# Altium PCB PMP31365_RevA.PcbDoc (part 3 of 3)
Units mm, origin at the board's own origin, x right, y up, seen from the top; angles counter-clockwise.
Board outline 134.61 x 49.53 mm, 4 copper layers (Top Layer, Layer 1, Layer 2, Bottom Layer), stack 1.787 mm thick; 183 components, 83 nets, 384 pads, 167 vias.
Unrouted connection lines stored in the file: 14.
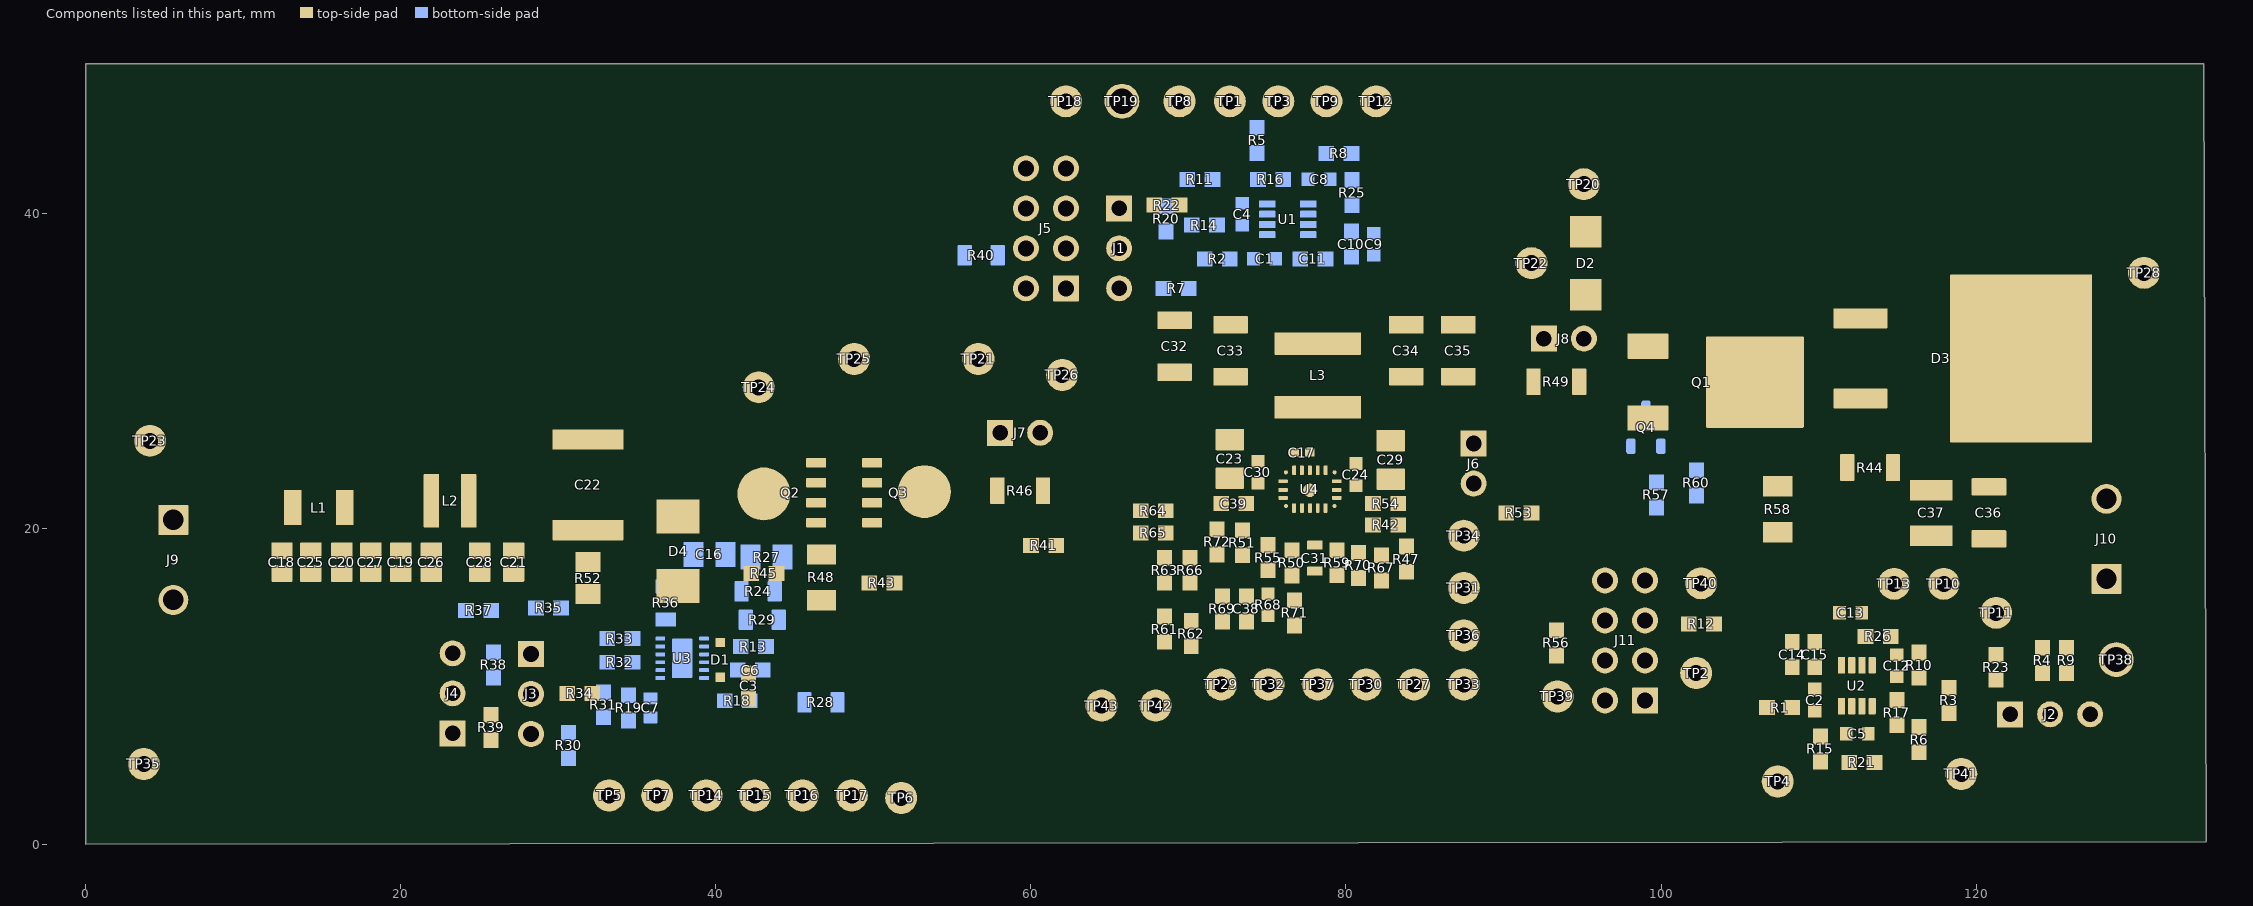
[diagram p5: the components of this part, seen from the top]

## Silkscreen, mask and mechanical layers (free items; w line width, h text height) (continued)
M10 Fab Notes:
  drawing of 189 lines, arcs and shapes, not listed
  text "DESIGN INFORMATION" at 741.376,161.675 h1.52
  text "MIN. TRACK WIDTH:" at 725.004,158.319 h1.52
  text "8" at 752.848,158.32 h1.52
  text "MIL" at 756.779,158.319 h1.52
  text "MIN. CLEARANCE:" at 725.004,155.167 h1.52
  text "7.874" at 748.5,155.167 h1.52
  text "MIL" at 756.779,155.167 h1.52
  text "MIN. VIA PAD SIZE:" at 725.004,152.014 h1.52
  text "24" at 752.087,152.014 h1.52
  text "MIL" at 756.779,152.014 h1.52
  text "0.05mm (2MIL)" at 742.657,148.714 h1.52
  text "MINIMUM ANNULAR RING" at 716.641,148.506 h1.52
  text "EXTERNAL" at 760.64,148.506 h1.52
  text "PER" at 721.721,145.708 h1.52
  text "IPC-D-275 CLASS 2 LEVEL C" at 727.309,145.708 h1.52
  text "MIL, HOLES" at 765.11,143.156 h1.52
  text "+/-" at 755.142,142.938 h1.52
  text "+/-" at 776.834,142.938 h1.52
  text "REGISTRATION TOLERANCES:" at 716.641,142.911 h1.52
  text "METAL" at 747.116,142.911 h1.52
  text "5" at 761.751,142.911 h1.52
  text "3" at 782.909,142.911 h1.52
  text "MIL" at 785.862,142.911 h1.52
  text "HOLE SIZE TOLERANCE (UNLESS OTHERWISE SPECIFIED):" at 716.641,140.414 h1.52
  text "+/-" at 776.834,140.341 h1.52
  text "3" at 782.909,140.314 h1.52
  text "MIL" at 785.862,140.314 h1.52
  text "MATERIAL:" at 714.742,136.818 h1.52
  text "FR-4 High Tg" at 739.798,133.553 h1.52
  text "X" at 736.129,133.35 h1.52
  text "FR-4" at 725.436,133.235 h1.52
  text "OTHER" at 763.231,133.235 h1.52
  text "62 MIL (1.6mm) +/-10%" at 733.566,129.602 h1.52
  text "X" at 730.516,129.54 h1.52
  text "THICKNESS:" at 716.641,129.394 h1.52
  text "OTHER" at 766.203,129.394 h1.52
  text "TOLERANCE:" at 716.641,125.88 h1.52
  text "X" at 738.187,125.88 h1.52
  text "ANSI IPC-6012 TYPE 3 CLASS 2" at 742.708,125.88 h1.52
  text "OTHER +/-" at 742.708,122.218 h1.52
  text "BOW & TWIST:" at 716.641,118.53 h1.52
  text "X" at 738.187,118.53 h1.52
  text "ANSI IPC-6012 TYPE 3 CLASS 2" at 742.708,118.53 h1.52
  text "OTHER +/-" at 742.708,114.804 h1.52
  text "DRILLING:" at 714.742,111.486 h1.52
  text "NC_DRILL FILES" at 759.472,108.815 h1.52
  text "REFERENCE:" at 716.641,108.715 h1.52
  text "X" at 733.335,108.712 h1.52
  text "AS SHOWN" at 737.856,108.715 h1.52
  text "X" at 756.221,108.715 h1.52
  text "OTHER" at 767.041,105.101 h1.52
  text "PTH COPPER THICKNESS:" at 716.633,105.012 h1.52
  text "X" at 745.57,105.012 h1.52
  text "20-30 um" at 748.821,105.012 h1.52
  text "BOARD FINISH:" at 714.742,101.263 h1.52
  text "SILKSCREEN:" at 718.685,98.466 h1.52
  text "X" at 743.013,98.466 h1.52
  text "TOP" at 745.984,98.466 h1.52
  text "X" at 755.967,98.466 h1.52
  text "BOTTOM" at 758.964,98.466 h1.52
  text "SILKSCREEN COLOR:" at 718.685,94.524 h1.52
  text "X" at 742.987,94.524 h1.52
  text "WHITE" at 745.984,94.524 h1.52
  text "OTHER" at 758.964,94.524 h1.52
  text "X" at 746.315,90.88 h1.52
  text "GREEN" at 749.312,90.88 h1.52
  text "OTHER" at 765.009,90.88 h1.52
  text "SOLDER RESIST COLOR:" at 718.685,90.706 h1.52
  text "X" at 746.315,86.962 h1.52
  text "MATTE" at 749.312,86.962 h1.52
  text "SEMI-GLOSS" at 764.997,86.946 h1.52
  text "IMMERSION GOLD (ENIG)" at 741.692,82.574 h1.52
  text "ENEPIG" at 775.665,82.39 h1.52
  text "SURFACE FINISH:" at 714.742,82.365 h1.52
  text "X" at 737.171,82.365 h1.52
  text "IMM. TIN/SILVER OR EQUIV" at 723.113,78.877 h1.52
  text "OTHER" at 759.472,78.777 h1.52
  text "ARRAY/PANEL:" at 714.742,74.831 h1.52
  text "CUT AND TRIM PER M1 BOARD OUTLINE" at 741.692,74.622 h1.52
  text "N.C. ROUTE" at 741.692,71.168 h1.52
  text "X" at 759.167,71.168 h1.52
  text "V. SCORE" at 763.688,71.168 h1.52
  text "CERTIFICATION:" at 714.742,67.888 h1.52
  text "MATERIALS AND WORKMANSHIP FOR ALL PCBS" at 733.157,67.888 h1.52
  text "TO MEET OR EXCEED THE REQUIREMENTS OF:" at 733.157,65.499 h1.52
  text "X" at 723.95,62.232 h1.52
  text "ANSI IPC-A-600F CLASS ->" at 727.201,62.232 h1.52
  text "X" at 769.06,62.232 h1.52
  text "2" at 771.854,62.232 h1.52
  text "1" at 763.853,62.194 h1.52
  text "3" at 780.846,62.194 h1.52
  text "X" at 744.575,58.481 h1.52
  text "RoHS" at 747.826,58.481 h1.52
  text "OTHER" at 764.194,58.481 h1.52
  text "PER ORDER" at 774.279,58.481 h1.52
  text "ALL BOARDS MUST MEET OR EXCEED UL94-V0 REQUIREMENTS." at 715.442,54.574 h1.52
  text "PCB MUST BEAR THE UL94V-0 UL REGISTERED MATERIAL ID NUMBER" at 715.442,51.626 h1.52
  text "ADDITIONAL REQUIREMENTS:" at 714.742,47.322 h1.52
  text "MICROSECTION:" at 716.641,44.601 h1.52
  text "YES" at 739.647,44.601 h1.52
  text "REQUIRED" at 761.529,40.935 h1.52
  text "BARE BOARD ELEC. TEST:" at 716.641,40.863 h1.52
  text "NONE" at 749.807,40.863 h1.52
  text "X" at 758.532,40.863 h1.52
  text "PER ORDER" at 776.566,40.863 h1.52
  text "XX MIL VIAS REQUIRE NON-CONDUCTIVE FILL AND PLANARIZE" at 720.912,35.657 h1.5
  text "XX MIL VIAS REQUIRE CONDUCTIVE FILL AND PLANARIZE" at 721.116,33.016 h1.52
  text "OUTER XX MIL TRACES REQUIRE 50 OHM SINGLE-ENDED IMPEDANCE" at 721.091,28.866 h1.47
  text "LAYER 2 & 3 (INNER LAYERS) XX MIL WIDE, XX MIL SPACE / TRACES REQUIRE 100 OHM DIFFERENTIAL IMPEDANCE" at 720.887,22.879 h1.52
  text ".Layer_Name" at 14.656,-21.806 h1.52
M11 Gerber Information:
  lines w0.254: -7.417,-23.626 160.223,-23.626 ; -7.417,-18.462 160.274,-18.462 ; -7.417,-13.297 -7.417,-28.791 94.31,-28.791 160.274,-28.791 160.274,-13.297 -7.404,-13.297 -7.404,-28.791 32.614,-28.791 ; 55.194,-28.791 55.194,-13.297 ; 87.376,-18.462 87.376,-13.297 ; 108.712,-18.462 108.712,-13.297 ; 124.511,-28.956 124.511,-23.804
  text "ALL ARTWORK VIEWED FROM TOP SIDE" at -5.804,-16.654 h1.52
  text "BOARD #:" at 57.099,-16.654 h1.52
  text ".PRJ_Number" at 70.955,-16.654 h1.52
  text "REV:" at 92.405,-16.654 h1.52
  text ".PCB_Rev" at 99.809,-16.654 h1.52
  text "SVN REV:" at 113.69,-16.654 h1.52
  text ".VersionControl_RevNumber" at 126.543,-16.654 h1.52
  text "LAYER NAME =" at -5.804,-21.806 h1.52
  text "PLOT NAME =" at -5.804,-27.034 h1.52
  text ".plot_File_Name" at 14.656,-27.034 h1.52
  text "GENERATED    :" at 57.15,-27.034 h1.52
  text ".Print_Date" at 79.235,-27.034 h1.52
  text ".Print_Time" at 97.752,-27.034 h1.52
  text "TEXAS INSTRUMENTS" at 129.87,-27.034 h1.52
M12 Stackup:
  drawing of 295 lines, arcs and shapes, not listed
  text "Layer" at 674.469,457.523 h1.52
  text "Name" at 684.88,457.523 h1.52
  text "Material" at 708.496,457.523 h1.52
  text "Thickness" at 730.334,457.523 h1.52
  text "Constant" at 746.84,457.523 h1.52
  text "Board Layer Stack" at 761.314,457.523 h1.52
  text "Top Overlay" at 684.88,454.475 h1.52
  text "Top Solder" at 684.88,451.427 h1.52
  text "Solder Resist" at 708.496,451.427 h1.52
  text "0.40mil" at 730.334,451.427 h1.52
  text "3.5" at 746.84,451.427 h1.52
  text "1" at 674.469,448.379 h1.52
  text "Top Layer" at 684.88,448.379 h1.52
  text "1.40mil" at 730.334,448.379 h1.52
  text "Dielectric 1" at 684.88,445.331 h1.52
  text "PP-006" at 708.496,445.331 h1.52
  text "2.80mil" at 730.334,445.331 h1.52
  text "4.1" at 746.84,445.331 h1.52
  text "2" at 674.469,442.283 h1.52
  text "Layer 1" at 684.88,442.283 h1.52
  text "CF-004" at 708.496,442.283 h1.52
  text "1.38mil" at 730.334,442.283 h1.52
  text "Dielectric1" at 684.88,439.235 h1.52
  text "FR-4 High Tg" at 708.496,439.235 h1.52
  text "59.20mil" at 730.334,439.235 h1.52
  text "4.8" at 746.84,439.235 h1.52
  text "3" at 674.469,436.187 h1.52
  text "Layer 2" at 684.88,436.187 h1.52
  text "CF-004" at 708.496,436.187 h1.52
  text "1.38mil" at 730.334,436.187 h1.52
  text "Dielectric 2" at 684.88,433.139 h1.52
  text "PP-006" at 708.496,433.139 h1.52
  text "2.80mil" at 730.334,433.139 h1.52
  text "4.1" at 746.84,433.139 h1.52
  text "4" at 674.469,430.091 h1.52
  text "Bottom Layer" at 684.88,430.091 h1.52
  text "1.40mil" at 730.334,430.091 h1.52
  text "Bottom Solder" at 684.88,427.043 h1.52
  text "Solder Resist" at 708.496,427.043 h1.52
  text "0.40mil" at 730.334,427.043 h1.52
  text "3.5" at 746.84,427.043 h1.52
  text "Bottom Overlay" at 684.88,423.995 h1.52
  text ".Layer_Name" at 14.656,-21.806 h1.52
M13 Component Bodies Top:
  text ".Layer_Name" at 14.656,-21.806 h1.52
M14 Component Bodies Bottom:
  text ".Layer_Name" at 14.656,-21.806 h1.52
M15 Courtyards Top:
  text ".Layer_Name" at 14.656,-21.806 h1.52
M16 Courtyards Bottom:
  text ".Layer_Name" at 14.656,-21.806 h1.52
Drill Drawing:
  text ".Layer_Name" at 14.656,-21.806 h1.52
M17 Embedded Cavity:
  text ".Layer_Name" at 14.656,-21.806 h1.52
M18 Embedded Assembly:
  text ".Layer_Name" at 14.656,-21.806 h1.52
M19 Embedded Keepout:
  text ".Layer_Name" at 14.91,-21.552 h1.52

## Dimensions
0,-10.16 to 25.4,-10.16 on M2 Board Dimensions
0,0 to 134.611,0.143 on M2 Board Dimensions
0,0 to 0,49.53 on M2 Board Dimensions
